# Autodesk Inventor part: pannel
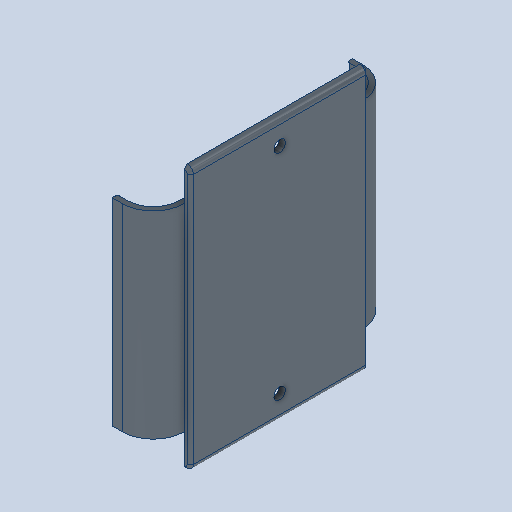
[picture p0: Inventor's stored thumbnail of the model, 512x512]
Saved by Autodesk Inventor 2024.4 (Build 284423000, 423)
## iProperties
Created: 2025-07
Part Number: pannel
Material: Generic
Document SubType Name: Modeling
Designer: AdminForWorker
Density: 1 g/cm^3
Appearance: Default
Title: pannel v2
Author: AdminForWorker
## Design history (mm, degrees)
feature "Body1"
body "Solid1"
